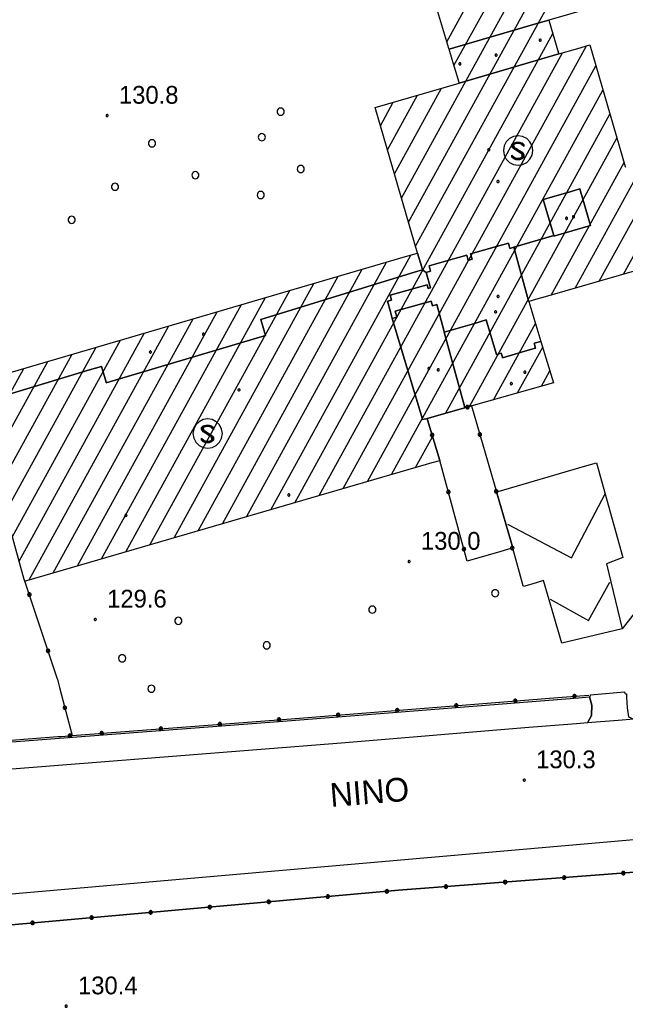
# Model space of a CAD drawing. Extents: x 513373 to 514978, y 5038576 to 5040180.
# Drawn here: x 513451.4 to 513502.4, y 5038585.3 to 5038668.6 of the extents above; entities that cross this region are included whole.
import ezdxf

# ---------------------------------------------------------------- set-up
doc = ezdxf.new("R2010")
doc.units = 0
for name, color, linetype in [('2010300', 7, 'Continuous'), ('3010204', 7, 'Continuous'), ('3030201', 7, 'Continuous'), ('3090300', 7, 'Continuous'), ('B1211', 7, 'Continuous'), ('C1131', 7, 'Continuous'), ('C12211', 7, 'Continuous'), ('C21159', 7, 'Continuous'), ('C2911', 7, 'Continuous'), ('CAMP_C12211', 7, 'Continuous'), ('Default', 7, 'Continuous'), ('F12107', 7, 'Continuous'), ('F12131', 7, 'Continuous'), ('F12132', 7, 'Continuous'), ('G4315', 7, 'Continuous'), ('TOP500', 7, 'Continuous'), ('TOP920', 7, 'Continuous')]:
    doc.layers.add(name, color=color, linetype=linetype)

# ---------------------------------------------------------------- blocks, each defined once
blk = doc.blocks.new('CAMP_2F84D089')
at = {"layer": 'CAMP_C12211'}
for p, q in [((5.082, 10.661), (15.666, 29.915)), ((5.687, 8.648), (16.26, 27.88)), ((1.258, -2.521), (16.853, 25.846)), ((1.852, -4.554), (17.446, 23.811)), ((2.446, -6.588), (18.039, 21.777)), ((-7.732, -28.214), (14.022, 11.356)), ((-3.657, -27.029), (16.875, 10.318)), ((-5.694, -27.622), (14.837, 9.724)), ((-1.619, -26.436), (17.653, 8.62)), ((0.664, -0.488), (4.64, 6.744)), ((0.07, 1.546), (2.601, 6.148)), ((0.418, -25.844), (18.247, 6.586)), ((-0.524, 3.579), (0.561, 5.552)), ((4.969, -20.681), (18.841, 4.553)), ((6.996, -20.107), (19.435, 2.52)), ((19.976, -8.95), (25.866, 1.764)), ((17.943, -9.535), (23.827, 1.168)), ((13.877, -10.703), (20.029, 0.486)), ((15.91, -10.119), (21.788, 0.573)), ((-9.769, -28.807), (2.037, -7.332)), ((-11.807, -29.399), (-0.003, -7.929)), ((-15.882, -30.585), (-4.084, -9.124)), ((-13.844, -29.992), (-2.043, -8.527)), ((-17.919, -31.177), (-6.124, -9.722)), ((-19.957, -31.77), (-8.164, -10.319)), ((-24.032, -32.955), (-12.245, -11.514)), ((-21.994, -32.362), (-10.204, -10.917)), ((-26.069, -33.548), (-14.285, -12.112)), ((-30.144, -34.733), (-18.365, -13.307)), ((-28.107, -34.14), (-16.325, -12.709)), ((9.02, -19.539), (12.56, -13.099)), ((-30.984, -33.147), (-20.405, -13.904)), ((-31.557, -31.075), (-22.446, -14.502)), ((-33.448, -28.287), (-26.526, -15.697)), ((-32.13, -29.004), (-24.486, -15.099)), ((11.048, -18.962), (13.172, -15.1)), ((-35.462, -28.837), (-28.566, -16.294)), ((-36.258, -27.171), (-30.606, -16.892)), ((13.077, -18.386), (13.783, -17.102)), ((2.456, -25.251), (3.884, -22.654))]:
    blk.add_line(p, q, dxfattribs=at)
blk = doc.blocks.new('03080200')
at = {"layer": 'Default'}
for p, q in [((-0.139, 0.046), (-0.146, 0)), ((-0.146, 0), (-0.139, -0.046)), ((-0.118, 0.086), (-0.139, 0.046)), ((-0.086, 0.118), (-0.118, 0.086)), ((-0.046, 0.139), (-0.086, 0.118)), ((0, 0.146), (-0.046, 0.139)), ((-0.042, 0.014), (-0.045, 0)), ((-0.045, 0), (-0.042, -0.014)), ((-0.036, 0.026), (-0.042, 0.014)), ((-0.026, 0.036), (-0.036, 0.026)), ((-0.014, 0.042), (-0.026, 0.036)), ((0, 0.045), (-0.014, 0.042)), ((0.046, 0.139), (0, 0.146)), ((0.014, 0.042), (0, 0.045)), ((0.026, 0.036), (0.014, 0.042)), ((0.036, 0.026), (0.026, 0.036)), ((0.042, 0.014), (0.036, 0.026)), ((0.045, 0), (0.042, 0.014)), ((0.042, -0.014), (0.045, 0)), ((0.086, 0.118), (0.046, 0.139)), ((0.118, 0.086), (0.086, 0.118)), ((0.139, 0.046), (0.118, 0.086)), ((0.146, 0), (0.139, 0.046)), ((0.139, -0.046), (0.146, 0)), ((-0.139, -0.046), (-0.118, -0.086)), ((-0.118, -0.086), (-0.086, -0.118)), ((-0.086, -0.118), (-0.046, -0.139)), ((-0.046, -0.139), (0, -0.146)), ((-0.042, -0.014), (-0.036, -0.026)), ((-0.036, -0.026), (-0.026, -0.036)), ((-0.026, -0.036), (-0.014, -0.042)), ((-0.014, -0.042), (0, -0.045)), ((0, -0.045), (0.014, -0.042)), ((0, -0.146), (0.046, -0.139)), ((0.014, -0.042), (0.026, -0.036)), ((0.026, -0.036), (0.036, -0.026)), ((0.036, -0.026), (0.042, -0.014)), ((0.046, -0.139), (0.086, -0.118)), ((0.086, -0.118), (0.118, -0.086)), ((0.118, -0.086), (0.139, -0.046))]:
    blk.add_line(p, q, dxfattribs=at)
blk = doc.blocks.new('08020400')
at = {"layer": 'Default'}
for p, q in [((-0.086, 0.028), (-0.09, 0)), ((-0.09, 0), (-0.086, -0.028)), ((-0.073, 0.053), (-0.086, 0.028)), ((-0.053, 0.073), (-0.073, 0.053)), ((-0.028, 0.086), (-0.053, 0.073)), ((0, 0.09), (-0.028, 0.086)), ((0.028, 0.086), (0, 0.09)), ((0.053, 0.073), (0.028, 0.086)), ((0.073, 0.053), (0.053, 0.073)), ((0.086, 0.028), (0.073, 0.053)), ((0.09, 0), (0.086, 0.028)), ((0.086, -0.028), (0.09, 0)), ((-0.086, -0.028), (-0.073, -0.053)), ((-0.073, -0.053), (-0.053, -0.073)), ((-0.053, -0.073), (-0.028, -0.086)), ((-0.028, -0.086), (0, -0.09)), ((0, -0.09), (0.028, -0.086)), ((0.028, -0.086), (0.053, -0.073)), ((0.053, -0.073), (0.073, -0.053)), ((0.073, -0.053), (0.086, -0.028))]:
    blk.add_line(p, q, dxfattribs=at)
blk = doc.blocks.new('NSIMB25')
at = {"layer": 'Default'}
for p, q in [((-0.086, 0.028), (-0.09, 0)), ((-0.09, 0), (-0.086, -0.028)), ((-0.073, 0.053), (-0.086, 0.028)), ((-0.053, 0.073), (-0.073, 0.053)), ((-0.028, 0.086), (-0.053, 0.073)), ((0, 0.09), (-0.028, 0.086)), ((0.028, 0.086), (0, 0.09)), ((0.053, 0.073), (0.028, 0.086)), ((0.073, 0.053), (0.053, 0.073)), ((0.086, 0.028), (0.073, 0.053)), ((0.09, 0), (0.086, 0.028)), ((0.086, -0.028), (0.09, 0)), ((-0.086, -0.028), (-0.073, -0.053)), ((-0.073, -0.053), (-0.053, -0.073)), ((-0.053, -0.073), (-0.028, -0.086)), ((-0.028, -0.086), (0, -0.09)), ((0, -0.09), (0.028, -0.086)), ((0.028, -0.086), (0.053, -0.073)), ((0.053, -0.073), (0.073, -0.053)), ((0.073, -0.053), (0.086, -0.028))]:
    blk.add_line(p, q, dxfattribs=at)
blk = doc.blocks.new('05010100')
at = {"layer": 'Default'}
for p, q in [((-0.143, 0.046), (-0.15, 0)), ((-0.15, 0), (-0.143, -0.046)), ((-0.121, 0.088), (-0.143, 0.046)), ((-0.088, 0.121), (-0.121, 0.088)), ((-0.046, 0.143), (-0.088, 0.121)), ((0, 0.15), (-0.046, 0.143)), ((0.046, 0.143), (0, 0.15)), ((0.088, 0.121), (0.046, 0.143)), ((0.121, 0.088), (0.088, 0.121)), ((0.143, 0.046), (0.121, 0.088)), ((0.15, 0), (0.143, 0.046)), ((0.143, -0.046), (0.15, 0)), ((-0.143, -0.046), (-0.121, -0.088)), ((-0.121, -0.088), (-0.088, -0.121)), ((-0.088, -0.121), (-0.046, -0.143)), ((-0.046, -0.143), (0, -0.15)), ((0, -0.15), (0.046, -0.143)), ((0.046, -0.143), (0.088, -0.121)), ((0.088, -0.121), (0.121, -0.088)), ((0.121, -0.088), (0.143, -0.046))]:
    blk.add_line(p, q, dxfattribs=at)
blk = doc.blocks.new('03030201')
at = {"layer": 'Default'}
for p, q in [((-0.728, 1.001), (-1.001, 0.728)), ((-0.382, 1.177), (-0.728, 1.001)), ((0, 1.237), (-0.382, 1.177)), ((0.382, 1.177), (0, 1.237)), ((0.728, 1.001), (0.382, 1.177)), ((1.001, 0.728), (0.728, 1.001)), ((-1.177, 0.382), (-1.238, 0)), ((-1.238, 0), (-1.177, -0.382)), ((-1.001, 0.728), (-1.177, 0.382)), ((-0.518, 0.508), (-0.368, 0.643)), ((-0.518, 0.358), (-0.518, 0.508)), ((-0.443, 0.223), (-0.518, 0.358)), ((-0.333, 0.584), (-0.451, 0.478)), ((-0.451, 0.478), (-0.451, 0.376)), ((-0.451, 0.376), (-0.389, 0.265)), ((-0.368, 0.148), (-0.443, 0.223)), ((-0.389, 0.265), (-0.326, 0.201)), ((-0.298, 0.526), (-0.383, 0.448)), ((-0.383, 0.448), (-0.383, 0.394)), ((-0.383, 0.394), (-0.335, 0.306)), ((-0.368, 0.643), (-0.158, 0.718)), ((0.148, -0.186), (-0.368, 0.148)), ((-0.335, 0.306), (-0.287, 0.257)), ((-0.147, 0.651), (-0.333, 0.584)), ((-0.326, 0.201), (0.183, -0.128)), ((-0.135, 0.583), (-0.298, 0.526)), ((-0.287, 0.257), (-0.18, 0.198)), ((-0.18, 0.198), (0.337, -0.137)), ((-0.158, 0.718), (0.127, 0.718)), ((0.115, 0.651), (-0.147, 0.651)), ((0.103, 0.583), (-0.135, 0.583)), ((0.266, 0.526), (0.103, 0.583)), ((0.301, 0.584), (0.115, 0.651)), ((0.127, 0.718), (0.337, 0.643)), ((0.487, 0.327), (0.266, 0.526)), ((0.487, 0.418), (0.301, 0.584)), ((0.337, 0.643), (0.487, 0.508)), ((0.487, 0.508), (0.487, 0.327)), ((1.177, 0.382), (1.001, 0.728)), ((1.238, 0), (1.177, 0.382)), ((1.177, -0.382), (1.238, 0)), ((-1.177, -0.382), (-1.001, -0.728)), ((-1.001, -0.728), (-0.728, -1.001)), ((-0.518, -0.39), (-0.298, -0.588)), ((-0.518, -0.572), (-0.518, -0.39)), ((-0.333, -0.647), (-0.518, -0.481)), ((-0.368, -0.707), (-0.518, -0.572)), ((-0.158, -0.782), (-0.368, -0.707)), ((-0.147, -0.714), (-0.333, -0.647)), ((-0.298, -0.588), (-0.135, -0.647)), ((0.127, -0.782), (-0.158, -0.782)), ((0.115, -0.714), (-0.147, -0.714)), ((-0.135, -0.647), (0.103, -0.647)), ((0.103, -0.647), (0.266, -0.588)), ((0.301, -0.647), (0.115, -0.714)), ((0.337, -0.707), (0.127, -0.782)), ((0.254, -0.245), (0.148, -0.186)), ((0.183, -0.128), (0.295, -0.191)), ((0.302, -0.293), (0.254, -0.245)), ((0.266, -0.588), (0.352, -0.512)), ((0.295, -0.191), (0.357, -0.253)), ((0.419, -0.542), (0.301, -0.647)), ((0.352, -0.382), (0.302, -0.293)), ((0.337, -0.137), (0.412, -0.212)), ((0.487, -0.572), (0.337, -0.707)), ((0.352, -0.512), (0.352, -0.382)), ((0.357, -0.253), (0.419, -0.364)), ((0.412, -0.212), (0.487, -0.347)), ((0.419, -0.364), (0.419, -0.542)), ((0.487, -0.347), (0.487, -0.572)), ((0.728, -1.001), (1.001, -0.728)), ((1.001, -0.728), (1.177, -0.382)), ((-0.728, -1.001), (-0.382, -1.177)), ((-0.382, -1.177), (0, -1.238)), ((0, -1.238), (0.382, -1.177)), ((0.382, -1.177), (0.728, -1.001))]:
    blk.add_line(p, q, dxfattribs=at)
blk = doc.blocks.new('A$C3704598A')
at = {"layer": '2010300'}
blk.add_lwpolyline([(126.48, -768.461), (129.344, -768.218)], dxfattribs=at)
at = {"layer": '3010204'}
blk.add_lwpolyline([(171.782, -708.472), (172.512, -710.49), (173.705, -713.959), (174.69, -717.991), (175.004, -721.069), (174.821, -724.119), (174.14, -727.369), (173.19, -730.21), (171.108, -733.178), (167.941, -736.272), (164.686, -739.027), (159.868, -742.062), (153.485, -745.877), (149.737, -748.062), (145.259, -751.056), (140.307, -753.932), (136.309, -756.274), (133.443, -758.512), (130.755, -760.841), (129.156, -762.908)], dxfattribs=at)
at = {"layer": '3090300'}
for points in [[(124.863, -756.915), (127.699, -751.515)], [(119.463, -754.079), (124.863, -756.915)], [(126.312, -762.199), (128.108, -758.963)], [(123.076, -760.403), (126.312, -762.199)]]:
    blk.add_lwpolyline(points, dxfattribs=at)
at = {"layer": 'B1211'}
blk.add_lwpolyline([(182.854, -779.395), (110.289, -784.942), (71.944, -788.357), (71.695, -785.89), (71.68, -785.737), (74.707, -785.49), (148.809, -779.036), (181.633, -776.874)], dxfattribs=at)
for points in [[(126.207, -770.822), (125.282, -770.893), (121.262, -771.205), (105.455, -772.523), (91.204, -773.673), (75.853, -774.87), (46.166, -777.392), (39.03, -777.882), (37.775, -777.377), (37.169, -775.785), (37.076, -775.539), (39.113, -775.552), (73.91, -772.72), (75.04, -772.628), (75.078, -772.63), (82.766, -772.041), (100.88, -770.652), (125.459, -768.701), (126.353, -768.63), (126.388, -768.62), (126.591, -769.326), (126.566, -770.204)], [(129.499, -768.38), (129.503, -768.536), (129.505, -768.659), (129.556, -769.565), (129.683, -770.31), (130.118, -770.52), (128.815, -770.62), (126.207, -770.822), (126.566, -770.204), (126.591, -769.326), (126.388, -768.62), (126.424, -768.6), (126.448, -768.577), (126.467, -768.547), (126.48, -768.508), (126.48, -768.461), (129.344, -768.218), (129.347, -768.247), (129.349, -768.267), (129.368, -768.312), (129.402, -768.35), (129.432, -768.367), (129.469, -768.378)]]:
    blk.add_lwpolyline(points, close=True, dxfattribs=at)
at = {"layer": 'C1131'}
for points in [[(128.338, -710.001), (122.96, -711.563), (121.954, -711.854), (114.538, -714.001), (114.522, -713.949), (112.322, -706.625)], [(131.815, -732.252), (122.84, -734.831), (121.833, -735.12), (121.263, -735.285), (121.249, -735.233), (119.998, -730.713), (123.369, -729.712), (123.385, -729.767), (126.461, -728.872), (125.565, -725.794), (124.559, -726.086), (122.489, -726.689), (123.369, -729.712), (119.998, -730.713), (119.669, -730.806), (119.548, -730.375), (118.54, -730.659), (116.355, -731.276), (116.481, -731.725), (116.15, -731.818), (116.028, -731.387), (115.352, -731.577), (115.02, -731.671), (112.862, -732.28), (112.989, -732.733), (112.619, -732.837), (112.295, -732.614), (112.235, -732.406), (111.883, -731.202), (108.3, -718.935), (115.398, -716.86), (123.801, -714.405), (125.398, -713.939), (126.404, -713.646), (129.397, -723.891), (129.413, -723.947)], [(74.53, -743.966), (84.217, -741.064), (85.22, -740.763), (85.609, -742.087), (85.626, -742.147), (99.057, -738.153), (98.666, -736.811), (111.351, -732.904), (111.902, -732.735), (112.295, -732.614), (112.619, -732.837), (112.983, -734.127), (112.771, -734.186), (112.686, -733.882), (111.889, -734.107), (111.678, -734.166), (109.561, -734.763), (109.675, -735.168), (109.348, -735.26), (109.602, -736.159), (109.757, -736.709), (112.315, -745.214), (112.32, -745.232), (112.688, -745.159), (112.717, -745.257), (113.762, -748.698), (113.616, -748.741), (112.898, -748.95), (112.61, -749.034), (78.911, -758.835), (78.767, -758.877), (78.747, -758.824), (78.714, -758.737), (77.128, -753.006)]]:
    blk.add_lwpolyline(points, dxfattribs=at)
for points in [[(123.801, -714.405), (115.398, -716.86), (115.381, -716.805), (115.11, -715.902), (114.882, -715.145), (114.799, -714.868), (114.538, -714.001), (121.954, -711.854), (122.96, -711.563), (123.785, -714.35)], [(126.461, -728.872), (123.385, -729.767), (123.369, -729.712), (122.489, -726.689), (124.559, -726.086), (125.565, -725.794)], [(121.263, -735.285), (122.291, -738.649), (121.71, -738.793), (121.837, -739.22), (121.41, -739.346), (119.055, -740.044), (119.037, -739.984), (118.933, -739.634), (118.545, -739.749), (117.682, -736.836), (116.678, -737.133), (114.137, -737.886), (114.121, -737.826), (113.5, -735.552), (113.145, -735.649), (113.04, -735.263), (112.029, -735.538), (109.99, -736.093), (110.13, -736.607), (109.757, -736.709), (109.602, -736.159), (109.348, -735.26), (109.675, -735.168), (109.561, -734.763), (111.678, -734.166), (111.889, -734.107), (112.686, -733.882), (112.771, -734.186), (112.983, -734.127), (112.619, -732.837), (112.989, -732.733), (112.862, -732.28), (115.02, -731.671), (115.352, -731.577), (116.028, -731.387), (116.15, -731.818), (116.481, -731.725), (116.355, -731.276), (118.54, -730.659), (119.548, -730.375), (119.669, -730.806), (119.998, -730.713), (121.249, -735.233)], [(112.295, -732.614), (111.902, -732.735), (111.351, -732.904), (98.666, -736.811), (99.057, -738.153), (85.626, -742.147), (85.609, -742.087), (85.22, -740.763), (84.217, -741.064), (74.53, -743.966), (73.524, -744.256), (71.2, -744.928), (71.19, -744.875), (70.879, -743.211), (72.044, -742.87), (110.878, -731.497), (111.883, -731.202), (112.235, -732.406)], [(114.137, -737.886), (115.861, -744.216), (115.873, -744.257), (115.577, -744.341), (112.688, -745.159), (112.32, -745.232), (112.315, -745.214), (109.757, -736.709), (110.13, -736.607), (109.99, -736.093), (112.029, -735.538), (113.04, -735.263), (113.145, -735.649), (113.5, -735.552), (114.121, -737.826)], [(122.291, -738.649), (123.357, -742.139), (116.586, -744.062), (116.442, -744.096), (115.873, -744.257), (115.861, -744.216), (114.137, -737.886), (116.678, -737.133), (117.682, -736.836), (118.545, -739.749), (118.933, -739.634), (119.037, -739.984), (119.055, -740.044), (121.41, -739.346), (121.837, -739.22), (121.71, -738.793)]]:
    blk.add_lwpolyline(points, close=True, dxfattribs=at)
at = {"layer": 'C12211'}
for points in [[(128.338, -710.001), (122.96, -711.563), (123.785, -714.35), (123.801, -714.405), (125.398, -713.939), (126.404, -713.646), (129.397, -723.891), (129.413, -723.947)], [(131.815, -732.252), (122.84, -734.831), (121.833, -735.12), (121.263, -735.285), (122.291, -738.649), (123.357, -742.139), (116.586, -744.062), (116.442, -744.096), (115.873, -744.257), (115.577, -744.341), (112.688, -745.159), (112.717, -745.257), (113.762, -748.698), (113.616, -748.741), (112.898, -748.95), (112.61, -749.034), (78.911, -758.835), (78.767, -758.877), (78.747, -758.824), (78.714, -758.737), (77.128, -753.006)], [(72.044, -742.87), (110.878, -731.497), (111.883, -731.202), (108.3, -718.935), (115.398, -716.86), (115.381, -716.805), (115.11, -715.902), (114.882, -715.145), (114.799, -714.868), (114.538, -714.001), (114.522, -713.949), (112.322, -706.625)]]:
    blk.add_lwpolyline(points, dxfattribs=at)
at = {"layer": 'C21159'}
blk.add_lwpolyline([(129.156, -762.907), (124.057, -764.111), (122.518, -758.83), (121.514, -759.129), (120.819, -759.337), (120.801, -759.274), (119.948, -756.214), (119.908, -756.071), (118.538, -751.339), (118.681, -751.298), (125.967, -749.176), (126.973, -748.884), (128.441, -754.142), (129.204, -756.872), (127.82, -757.403), (128.956, -762.083)], close=True, dxfattribs=at)
at = {"layer": 'C2911'}
for points in [[(116.442, -744.096), (118.538, -751.339), (119.908, -756.071), (118.901, -756.362), (116.072, -757.18), (116.018, -756.982), (113.762, -748.698), (112.717, -745.257), (112.688, -745.159), (115.577, -744.341), (115.873, -744.257), (116.442, -744.096)], [(81.502, -767.129), (78.767, -758.877)], [(81.502, -767.129), (81.603, -767.515), (81.69, -767.847), (82.751, -771.892)], [(82.751, -771.892), (100.868, -770.502), (124.095, -768.659), (126.332, -768.482)], [(75.079, -772.481), (81.537, -771.985), (81.84, -771.962), (82.751, -771.892)], [(71.944, -788.357), (110.289, -784.942), (182.854, -779.395)]]:
    blk.add_lwpolyline(points, dxfattribs=at)
at = {"layer": '3030201'}
for p in [(120.362, -722.554), (94.181, -746.424)]:
    blk.add_blockref('03030201', p, dxfattribs=at)
at = {"layer": 'C2911'}
for p, rotation in [((116.105, -744.192), 15.798175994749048), ((113.108, -746.545), 106.88094921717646), ((117.137, -746.498), -73.86009569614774), ((114.484, -751.352), 105.23373762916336), ((118.527, -751.301), -73.86009569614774), ((115.798, -756.176), 105.23373762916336), ((119.875, -756.08), -163.8622823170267), ((79.142, -760.01), 108.33617254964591), ((80.715, -764.756), 108.33617254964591), ((125.121, -768.578), 4.536815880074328), ((82.136, -769.547), -75.30698533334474), ((115.153, -769.369), 4.536816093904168), ((120.137, -768.973), 4.536816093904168), ((105.184, -770.16), 4.536816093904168), ((110.168, -769.764), 4.536816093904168), ((90.229, -771.318), 4.3864523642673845), ((95.214, -770.936), 4.3864523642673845), ((100.199, -770.553), 4.3864523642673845), ((82.557, -771.907), 4.389252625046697), ((85.243, -771.701), 4.3864523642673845), ((129.237, -783.494), 4.371974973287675), ((114.281, -784.637), 4.371974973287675), ((119.267, -784.256), 4.371974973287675), ((124.252, -783.875), 4.371974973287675), ((104.316, -785.474), 5.088581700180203), ((109.297, -785.031), 5.088581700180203), ((99.336, -785.918), 5.088581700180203), ((89.375, -786.805), 5.088581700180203), ((94.356, -786.361), 5.088581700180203), ((79.415, -787.692), 5.088581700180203), ((84.395, -787.248), 5.088581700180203)]:
    blk.add_blockref('03080200', p, dxfattribs=dict(at, rotation=rotation))
at = {"layer": 'CAMP_C12211'}
blk.add_blockref('CAMP_2F84D089', (109.269, -724.04), dxfattribs=at)
at = {"layer": 'F12107'}
for p in [(85.7, -719.608), (111.173, -757.224), (84.703, -762.1), (120.889, -775.651), (82.246, -794.719)]:
    blk.add_blockref('08020400', p, dxfattribs=at)
at = {"layer": 'F12131'}
for p in [(118.507, -714.505), (117.885, -722.487), (125.038, -728.141), (118.471, -736.168), (89.347, -739.547), (113.626, -741.05), (120.938, -741.25), (87.289, -753.33)]:
    blk.add_blockref('NSIMB25', p, dxfattribs=at)
at = {"layer": 'F12132'}
for p in [(122.232, -713.258), (115.459, -715.246), (118.671, -725.169), (124.456, -728.275), (118.674, -734.862), (93.825, -738.052), (112.843, -740.927), (96.825, -742.749), (119.793, -742.216), (101.025, -751.606)]:
    blk.add_blockref('NSIMB25', p, dxfattribs=at)
at = {"layer": 'G4315', "xscale": 2, "yscale": 2}
for p in [(100.34, -719.278), (98.751, -721.432), (89.484, -721.953), (93.146, -724.637), (102.034, -724.113), (86.366, -725.612), (98.658, -726.307), (82.714, -728.4), (118.431, -759.892), (108.073, -761.271), (91.705, -762.222), (99.164, -764.287), (86.966, -765.38), (89.438, -767.946)]:
    blk.add_blockref('05010100', p, dxfattribs=at)
at = {"layer": 'TOP500'}
blk.add_text('NINO', height=2, rotation=4.6717, dxfattribs=at).set_placement((104.581, -777.926))
at = {"layer": 'TOP920'}
for s, p in [('130.8', (86.7, -718.608)), ('130.0', (112.173, -756.224)), ('129.6', (85.703, -761.1)), ('130.3', (121.889, -774.651)), ('130.4', (83.246, -793.719))]:
    blk.add_text(s, height=1.5, dxfattribs=at).set_placement(p)

msp = doc.modelspace()

# ---------------------------------------------------------------- block references
at = {"layer": 'Default'}
msp.add_blockref('A$C3704598A', (513373.046, 5039380.14), dxfattribs=at)

doc.saveas('drawing.dxf')
